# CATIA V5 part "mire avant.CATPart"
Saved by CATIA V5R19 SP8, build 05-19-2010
Part number: mire avant
Bounding box of the stored display mesh (mm): x -2 to 2, y -4.5 to 4.5, z -4 to 1
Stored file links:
  C:\Users\Arthur\Desktop\Catia parts\GLOCK\Ensemble culasse\mire avant.CATPart
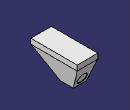
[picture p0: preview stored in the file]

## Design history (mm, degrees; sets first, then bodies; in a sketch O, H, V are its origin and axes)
Set1
  Sketch1 on xy-plane, origin (0, 0, 0), H (1, 0, 0), V (0, 1, 0)
    line L1 (2, 4.5) -> (2, -4.5)
    line L2 (2, -4.5) -> (-2, -4.5)
    line L3 (-2, -4.5) -> (-2, 4.5)
    line L4 (-2, 4.5) -> (2, 4.5)
    length L1 = 9
    length L4 = 4
    vertical: L1 V, L3 V
    horizontal: L2 H, L4 H
    equidistance: L1 L3 O, L2 L4 O
Body1 (main body)
  Pad1: profile Sketch1, direction (0, 0, 1), length 1
  Plane1: type Offset, RefPlane xy-plane, Offset 4, reversed
  Boundary1: Boundary {extract ExtractElem start face of Pad1}
  Sketch2 on Plane1, origin (0, 0, -4), H (1, 0, 0), V (0, 1, 0)
    line L1 (1.25, 3) -> (-1.25, 3)
    line L2 (-1.25, 3) -> (-1.25, 0.5)
    line L3 (-1.25, 0.5) -> (1.25, 0.5)
    line L4 (1.25, 0.5) -> (1.25, 3)
    axis line L5 (0, -12.8226) -> (0, 7.1774)
    point P5 (0, -12.8226)
    length L1 = 2.5
    length L2 = 2.5
    distance L1 H = 3
    horizontal: L1 H, L3 H
    vertical: L2 V, L4 V, L5 V
    coincidence: P5 V
    symmetry: L4 L2 L5
  Loft1: solid, Sections (Sketch2; Sketch1)
  Sketch3 on face of Loft1, origin (0, 3.8335, -1.7773), H (-1, 0, 0), V (0, 0.3511, 0.9363)
    circle A1 centre (0, -1) radius 1
    point P1 (0, -1)
    radius A1 = 1
    distance P1 H = 1
    coincidence: P1 V
  Pocket1: profile Sketch3, direction (0, -0.9363, 0.3511), length 0.1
